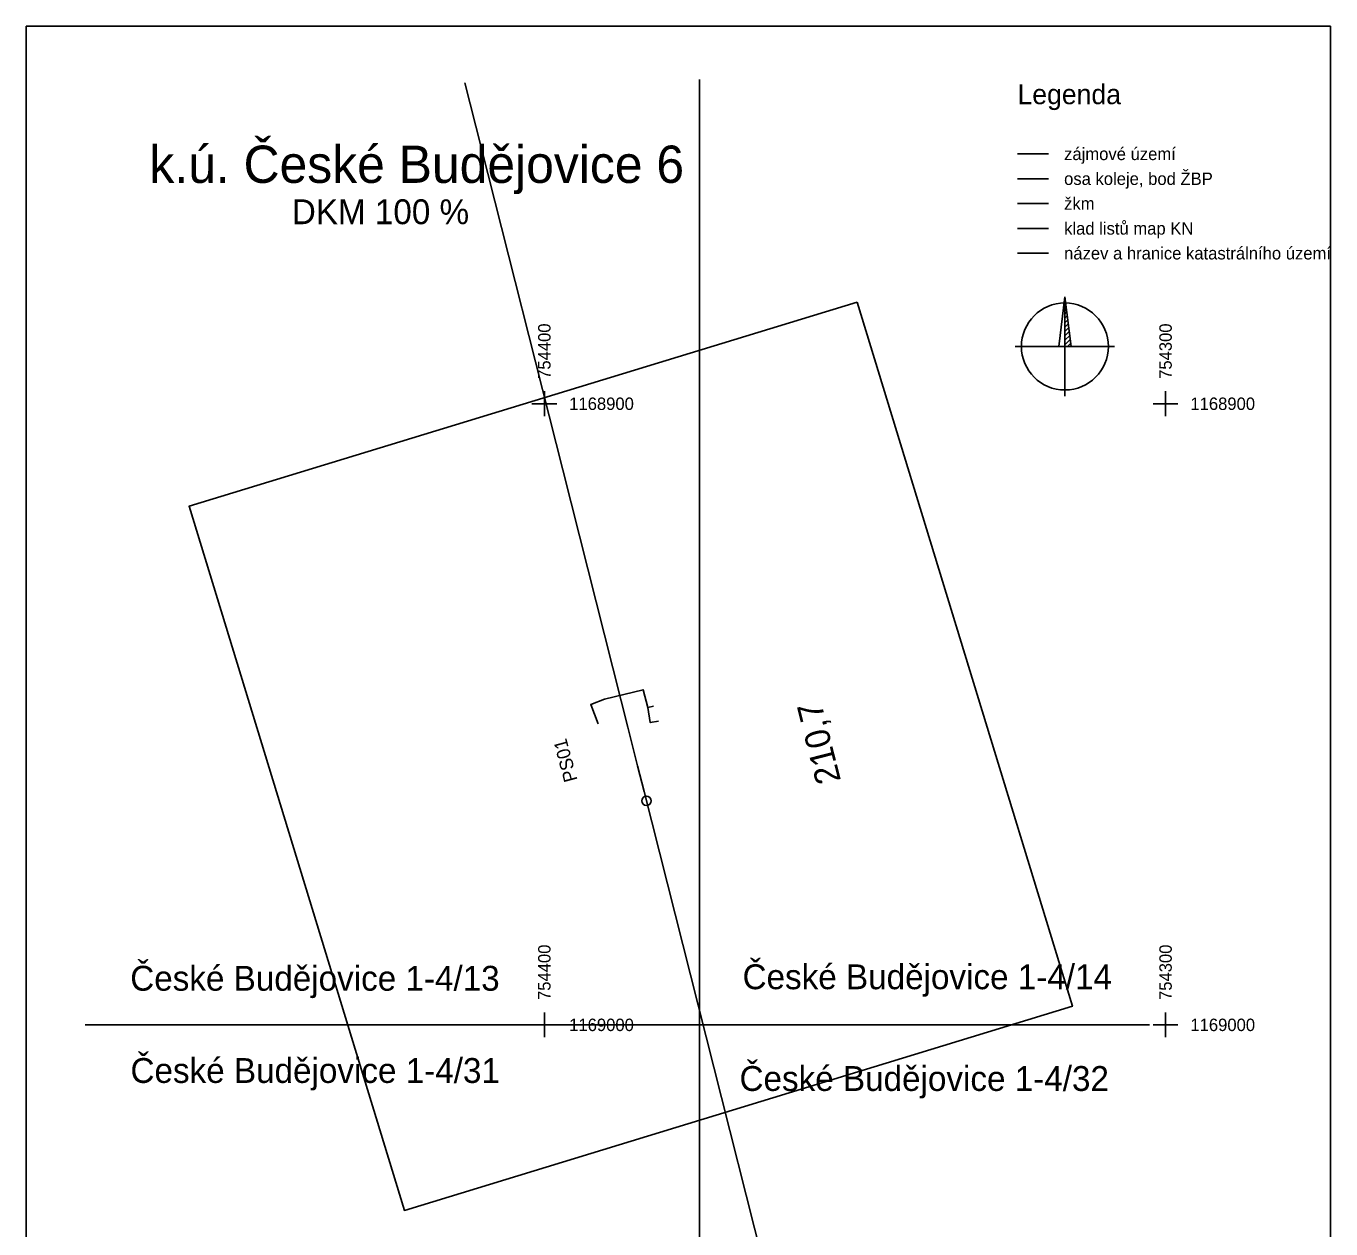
# Model space of a CAD drawing. Extents: x -754611 to -754273, y -1169136 to -1168342.
# Drawn here: x -754483.4 to -754273.4, y -1169032.9 to -1168839.2 of the extents above; entities that cross this region are included whole.
import ezdxf

# ---------------------------------------------------------------- set-up
doc = ezdxf.new("R2010")
doc.units = 0
for name, color, linetype in [('Implicitní', 7, 'Continuous'), ('Vrstva 1', 7, 'Continuous'), ('Vrstva 13', 7, 'Continuous'), ('Vrstva 23', 7, 'Continuous'), ('Vrstva 24', 7, 'Continuous'), ('Vrstva 3', 7, 'Continuous'), ('Vrstva 45', 7, 'Continuous'), ('Vrstva 61', 7, 'Continuous'), ('Vrstva 62', 7, 'Continuous'), ('Vrstva 63', 7, 'Continuous'), ('Vrstva 7', 7, 'Continuous')]:
    doc.layers.add(name, color=color, linetype=linetype)

msp = doc.modelspace()

# ---------------------------------------------------------------- linework, layer by layer
at = {"layer": 'Implicitní'}
for points in [[(-754400, -1168902), (-754400, -1168900), (-754400, -1168898)], [(-754402, -1168900), (-754400, -1168900), (-754398, -1168900)]]:
    msp.add_lwpolyline(points, dxfattribs=at)
at = {"layer": 'Vrstva 1'}
for p, q in [((-754410.17, -1168858.68), (-754412.78, -1168848.33)), ((-754323.83, -1168863.77), (-754318.83, -1168863.77))]:
    msp.add_line(p, q, dxfattribs=at)
msp.add_lwpolyline([(-754360.86, -1169053.76), (-754371.5, -1169011.68), (-754383.94, -1168962.43), (-754384.99, -1168958.29), (-754386.56, -1168952.08), (-754387.62, -1168947.84), (-754397.03, -1168910.64), (-754410.17, -1168858.68)], dxfattribs=at)
msp.add_circle((-754383.57, -1168963.93), 0.75, dxfattribs=at)
at = {"layer": 'Vrstva 13'}
msp.add_line((-754323.83, -1168875.77), (-754318.83, -1168875.77), dxfattribs=at)
at = {"layer": 'Vrstva 23'}
msp.add_line((-754323.83, -1168859.77), (-754318.83, -1168859.77), dxfattribs=at)
msp.add_lwpolyline([(-754349.65, -1168883.63), (-754457.19, -1168916.51), (-754422.53, -1169029.88), (-754314.99, -1168997.01)], close=True, dxfattribs=at)
at = {"layer": 'Vrstva 3'}
msp.add_line((-754323.83, -1168871.77), (-754318.83, -1168871.77), dxfattribs=at)
for points in [[(-754375, -1168847.8), (-754375, -1169000), (-754473.93, -1169000)], [(-754302.6, -1169000), (-754375, -1169000), (-754375, -1168847.8)], [(-754300, -1168902), (-754300, -1168900), (-754300, -1168898)], [(-754302, -1168900), (-754300, -1168900), (-754298, -1168900)], [(-754400, -1169002), (-754400, -1169000), (-754400, -1168998)], [(-754300, -1169002), (-754300, -1169000), (-754300, -1168998)], [(-754473.93, -1169000), (-754375, -1169000), (-754375, -1169050.73)], [(-754402, -1169000), (-754400, -1169000), (-754398, -1169000)], [(-754375, -1169054.99), (-754375, -1169000), (-754307.55, -1169000)], [(-754302, -1169000), (-754300, -1169000), (-754298, -1169000)]]:
    msp.add_lwpolyline(points, dxfattribs=at)
at = {"layer": 'Vrstva 45'}
for points in [[(-754391.33, -1168951.52), (-754392.52, -1168948.41), (-754390.32, -1168947.54), (-754384.1, -1168946.05), (-754383.34, -1168948.91)], [(-754382.42, -1168948.71), (-754383.34, -1168948.91)], [(-754383.34, -1168948.91), (-754382.96, -1168951.34), (-754381.64, -1168951.09)]]:
    msp.add_lwpolyline(points, dxfattribs=at)
at = {"layer": 'Vrstva 61'}
msp.add_line((-754273.43, -1168839.2), (-754483.43, -1168839.2), dxfattribs=at)
msp.add_lwpolyline([(-754483.43, -1168839.2), (-754483.43, -1169136.2), (-754273.43, -1169136.2), (-754273.43, -1168839.2)], dxfattribs=at)
at = {"layer": 'Vrstva 62'}
for p, q in [((-754316.2, -1168882.78), (-754316.2, -1168898.78)), ((-754316.2, -1168883.42), (-754316.13, -1168883.34)), ((-754316.2, -1168884.12), (-754316.05, -1168883.97)), ((-754316.2, -1168884.83), (-754315.97, -1168884.6)), ((-754316.2, -1168885.54), (-754315.89, -1168885.23)), ((-754316.2, -1168886.24), (-754315.81, -1168885.86)), ((-754316.2, -1168886.95), (-754315.73, -1168886.49)), ((-754316.2, -1168887.66), (-754315.65, -1168887.12)), ((-754316.2, -1168888.37), (-754315.58, -1168887.74)), ((-754316.2, -1168889.07), (-754315.5, -1168888.37)), ((-754316.2, -1168889.78), (-754315.42, -1168889)), ((-754324.2, -1168890.78), (-754308.2, -1168890.78)), ((-754316.2, -1168890.49), (-754315.34, -1168889.63)), ((-754315.78, -1168890.78), (-754315.26, -1168890.26))]:
    msp.add_line(p, q, dxfattribs=at)
for points in [[(-754316.2, -1168882.78), (-754317.2, -1168890.78)], [(-754316.2, -1168882.78), (-754316.2, -1168890.78), (-754315.2, -1168890.78), (-754316.2, -1168882.78)]]:
    msp.add_lwpolyline(points, dxfattribs=at)
msp.add_circle((-754316.2, -1168890.78), 7, dxfattribs=at)
at = {"layer": 'Vrstva 7'}
msp.add_line((-754323.83, -1168867.77), (-754318.83, -1168867.77), dxfattribs=at)

# ---------------------------------------------------------------- texts
at = {"layer": 'Implicitní'}
msp.add_text('754400', height=2, rotation=90, dxfattribs=at).set_placement((-754399, -1168896))
msp.add_text('1168900', height=2, dxfattribs=at).set_placement((-754396, -1168901))
at = {"layer": 'Vrstva 13'}
msp.add_text('název a hranice katastrálního území', height=2, dxfattribs=at).set_placement((-754316.33, -1168876.77))
at = {"layer": 'Vrstva 23'}
msp.add_text('zájmové území', height=2, dxfattribs=at).set_placement((-754316.33, -1168860.77))
at = {"layer": 'Vrstva 24'}
for s, height, p in [('k.ú. České Budějovice 6', 6, (-754463.58, -1168864.44)), ('DKM 100 %', 4, (-754440.65, -1168871.09))]:
    msp.add_text(s, height=height, dxfattribs=at).set_placement(p)
at = {"layer": 'Vrstva 3'}
for s, height, p in [('klad listů map KN', 2, (-754316.33, -1168872.77)), ('1168900', 2, (-754296, -1168901)), ('České Budějovice 1-4/13', 4, (-754466.66, -1168994.5)), ('České Budějovice 1-4/14', 4, (-754368.09, -1168994.26)), ('1169000', 2, (-754396, -1169001)), ('1169000', 2, (-754296, -1169001)), ('České Budějovice 1-4/31', 4, (-754466.62, -1169009.35)), ('České Budějovice 1-4/32', 4, (-754368.58, -1169010.64))]:
    msp.add_text(s, height=height, dxfattribs=at).set_placement(p)
for s, height, rotation, p in [('754300', 2, 90, (-754299, -1168896)), ('PS01', 2.16, 105, (-754394.65, -1168960.58)), ('754400', 2, 90, (-754399, -1168996)), ('754300', 2, 90, (-754299, -1168996))]:
    msp.add_text(s, height=height, rotation=rotation, dxfattribs=at).set_placement(p)
at = {"layer": 'Vrstva 62'}
msp.add_text('Legenda', height=3.2, dxfattribs=at).set_placement((-754323.83, -1168851.77))
at = {"layer": 'Vrstva 63'}
msp.add_text('osa koleje, bod ŽBP', height=2, dxfattribs=at).set_placement((-754316.33, -1168864.77))
at = {"layer": 'Vrstva 7'}
msp.add_text('žkm', height=2, dxfattribs=at).set_placement((-754316.33, -1168868.77))
msp.add_text('210,7', height=4, rotation=104.1774, dxfattribs=at).set_placement((-754352.23, -1168960.67))

doc.saveas('drawing.dxf')
